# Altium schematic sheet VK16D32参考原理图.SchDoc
size A4
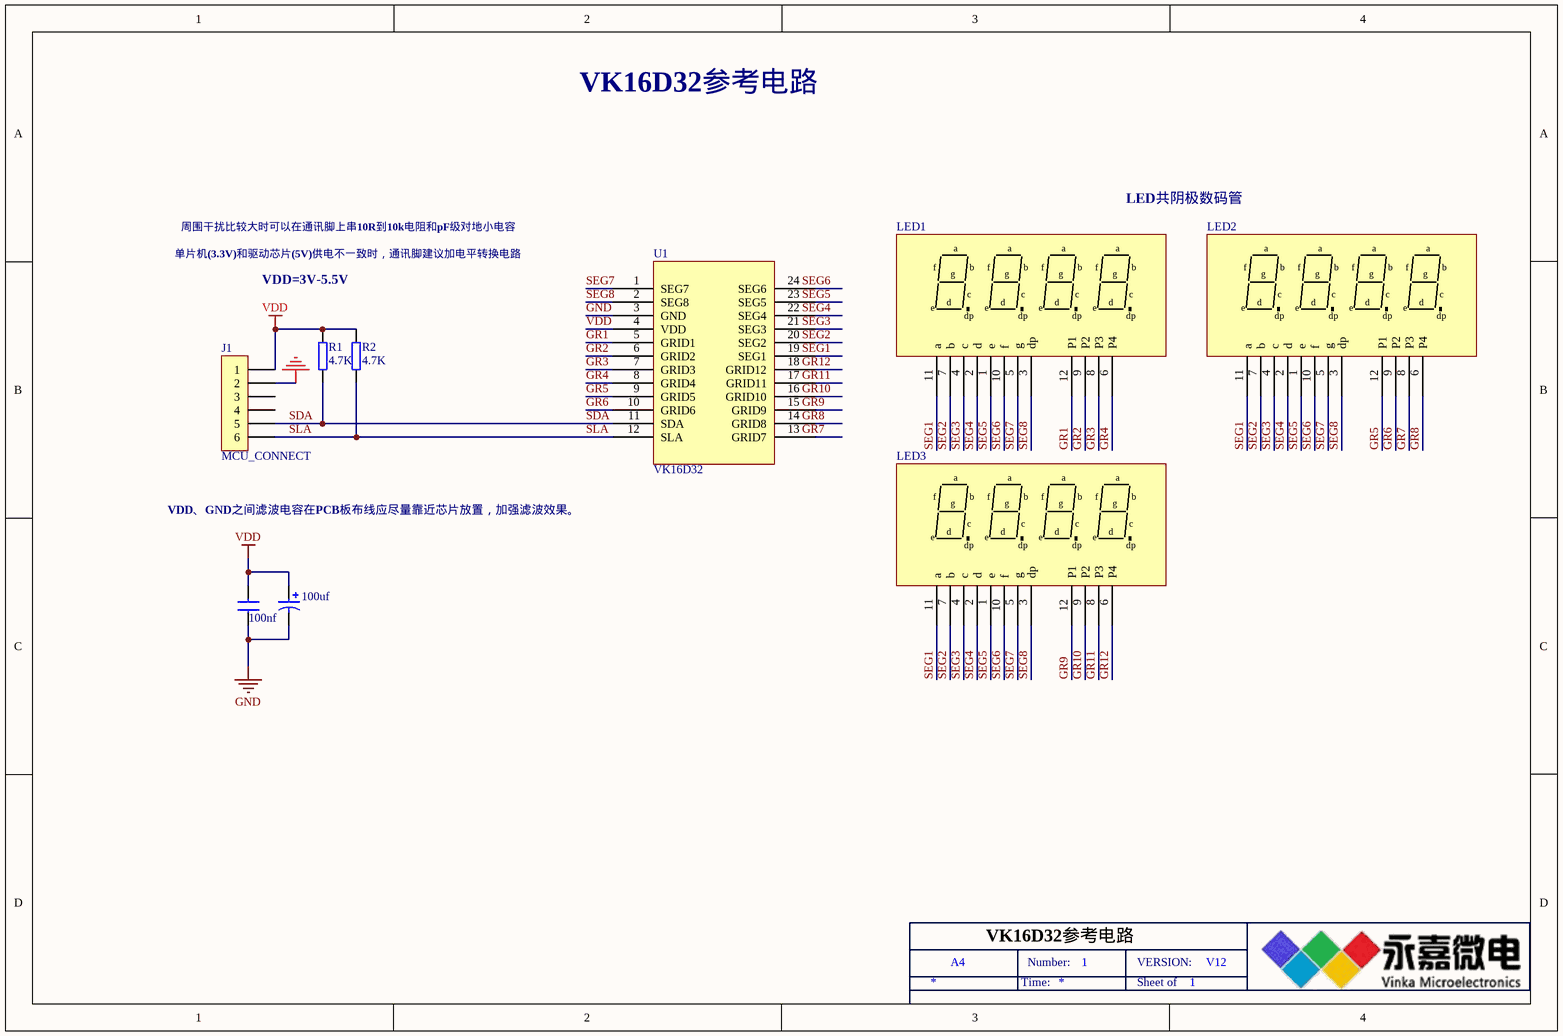
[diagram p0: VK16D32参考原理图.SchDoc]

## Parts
100nf  CAP  (value not drawn)
100uf  CAP2  (value not drawn)
J1  MCU_CONNECT
LED1  (no value)
LED2  (no value)
LED3  (no value)
R1  4.7K  [0603-R]
R2  4.7K  [0603-R]
U1  VK16D32

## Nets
GND: 100nf.2 100uf.2 J1.2 U1.3(GND)
VDD: 100nf.1 100uf.1 J1.1 R1.1 R2.1 U1.4(VDD)
GR1: LED1.12(P1) U1.5(GRID1)
GR2: LED1.9(P2) U1.6(GRID2)
GR3: LED1.8(P3) U1.7(GRID3)
GR4: LED1.6(P4) U1.8(GRID4)
GR5: LED2.12(P1) U1.9(GRID5)
GR6: LED2.9(P2) U1.10(GRID6)
GR7: LED2.8(P3)
GR8: LED2.6(P4)
GR9: LED3.12(P1)
GR10: LED3.9(P2)
GR11: LED3.8(P3)
GR12: LED3.6(P4)
SDA: J1.5 R1.2 U1.11(SDA)
SEG1: LED1.11(a) LED2.11(a) LED3.11(a)
SEG2: LED1.7(b) LED2.7(b) LED3.7(b)
SEG3: LED1.4(c) LED2.4(c) LED3.4(c)
SEG4: LED1.2(d) LED2.2(d) LED3.2(d)
SEG5: LED1.1(e) LED2.1(e) LED3.1(e)
SEG6: LED1.10(f) LED2.10(f) LED3.10(f)
SEG7: LED1.5(g) LED2.5(g) LED3.5(g) U1.1(SEG7)
SEG8: LED1.3(dp) LED2.3(dp) LED3.3(dp) U1.2(SEG8)
SLA: J1.6 R2.2 U1.12(SLA)

Not connected (* = marked no-connect by the designer): J1 3 4; U1 13(GRID7) 14(GRID8) 15(GRID9) 16(GRID10) 17(GRID11) 18(GRID12) 19(SEG1) 20(SEG2) 21(SEG3) 22(SEG4) 23(SEG5) 24(SEG6)

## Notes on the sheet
- VK16D32参考电路
- 周围干扰比较大时可以在通讯脚上串10R到10k电阻和pF级对地小电容
- LED共阴极数码管
- 单片机(3.3V)和驱动芯片(5V)供电不一致时，通讯脚建议加电平转换电路
- VDD=3V-5.5V
- VDD、GND之间滤波电容在PCB板布线应尽量靠近芯片放置，加强滤波效果。
- A4
- Time:
- Number:
- 1
- Sheet of
- VERSION:
- V12
- Labels drawn without touching a wire or pin: GR7, GR8, GR9, GR10, GR11, GR12, SEG1, SEG2, SEG3, SEG4, SEG5, SEG6

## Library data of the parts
100nf = CAP: Capacitor
100uf = CAP2: Bi-Polar Capacitor
J1 = CON6: Connector
LED1-LED3 = Component_1
R1 R2 = RES: Resistor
